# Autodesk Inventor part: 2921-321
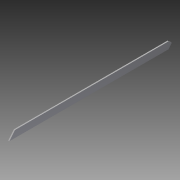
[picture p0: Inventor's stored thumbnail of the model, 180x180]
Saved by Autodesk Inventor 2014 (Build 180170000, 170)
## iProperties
Company: NHTSA/VRTC
Created: 2011-11
Part Number: 2921-321
Material: Steel
Document SubType Name: Modeling
Designer: Mike Vanvoorhis
Density: 7.85 g/cm^3
Project: CHILD SIDE IMPACT SLED
Description: BENCH TOP ANCHOR BRACE PLATE
Mass: 2134.44 g
Surface Area: 997.85 cm^2
Volume: 271.903 cm^3
Appearance: Steel
Stock Number: BAR 38.1 (1 1/2") x 6.4 (1/4") x 900.0 (35 7/16")
DESIGN DATE: 2012-11-05
Author: Dave Walker
Title: Bench Top Anchor Brace Plate
Subject: Chils Side Impact Sled
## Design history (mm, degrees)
node "Sketch1"
node "2921-2061"
sketch "Sketch2"
  geometry: L1 (38.1, -0.855)-(38.1, 1089.375) reference; L2 (38.1, 1089.375)-(0, 1121.345) reference; L3 (0, 1121.345)-(0, 0) reference; L4 (0, 880.886)-(38.1, 848.916); L5 (0, 880.886)-(0, 1121.345); L6 (0, 1121.345)-(38.1, 1089.375); L7 (38.1, 1089.375)-(38.1, 848.916); 1 further point
  constraints: 8 end point, 2 point on line, 1 collinear, 1 parallel
  dimensions: "d0" = 50 deg angle of L4 L3; "d1" = 900 vertical distance of L4.start point (22.779, -19.114)
extrude "Extrusion1" cut sketch "Sketch2" stored distance "d2" = 10; taper "d3" = 0 deg
node "2921-206"
node "Base1"
